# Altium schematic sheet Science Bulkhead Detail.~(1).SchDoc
size B; Organization: Monterey Bay Aquarium Research Institute; Address1: 7700 Sandholdt Rd; Address2: Moss Landing, CA 95039-9644; CompanyName: MBARI
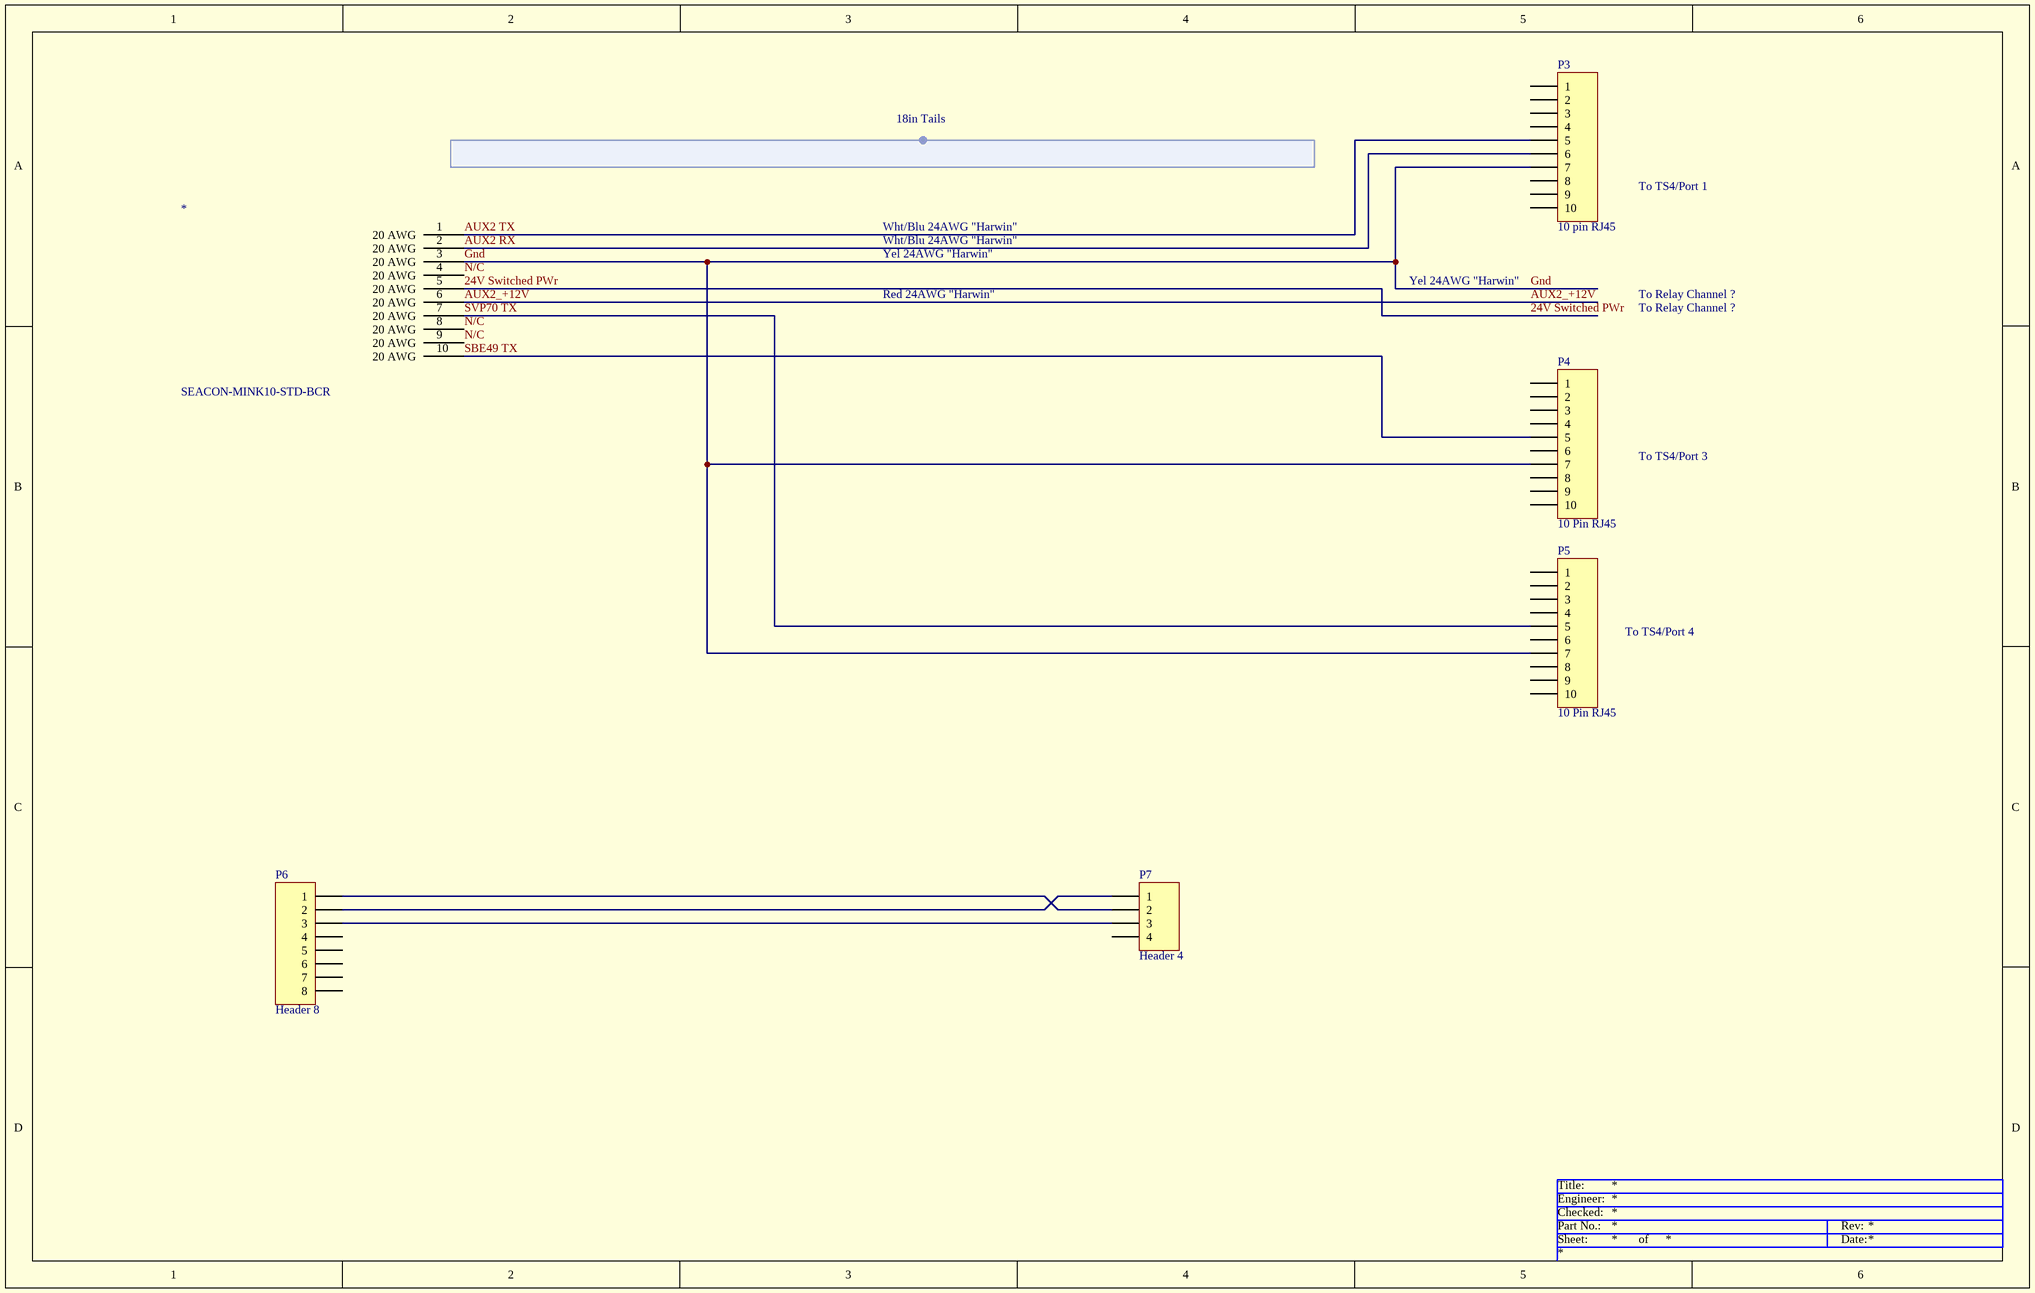
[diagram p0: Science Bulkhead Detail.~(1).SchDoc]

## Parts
*  SEACON-MINK10-STD-BCR
P3  10 pin RJ45  [HDR1X10]
P4  10 Pin RJ45  [HDR1X10]
P5  10 Pin RJ45  [HDR1X10]
P6  Header 8  [HDR1X8]
P7  Header 4  [HDR1X4]

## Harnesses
18in Tails: 

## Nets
24V Switched PWr: *.5(20_AWG)
AUX2 RX: *.2(20_AWG) P3.6
AUX2 TX: *.1(20_AWG) P3.5
AUX2_+12V: *.6(20_AWG)
Gnd: *.3(20_AWG) P3.7 P4.7 P5.7
N/C: *.4(20_AWG) *.8(20_AWG) *.9(20_AWG)
SBE49 TX: *.10(20_AWG) P4.5
SVP70 TX: *.7(20_AWG) P5.5
NetP6_1: P6.1 P7.2
NetP6_2: P6.2 P7.1
NetP6_3: P6.3 P7.3

Not connected (* = marked no-connect by the designer): P3 1 2 3 4 8 9 10; P4 1 2 3 4 6 8 9 10; P5 1 2 3 4 6 8 9 10; P6 4 5 6 7 8; P7 4

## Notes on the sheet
- Wht/Blu 24AWG "Harwin"
- To TS4/Port 1
- Yel 24AWG "Harwin"
- Red 24AWG "Harwin"
- To Relay Channel ?
- To TS4/Port 3
- To TS4/Port 4

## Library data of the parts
* = SEACON-MINK10-STD-BCR: Seacon MINK10 BCR Standard Length
P3-P5 = Header 10: Header, 10-Pin
P6 = Header 8: Header, 8-Pin
P7 = Header 4: Header, 4-Pin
